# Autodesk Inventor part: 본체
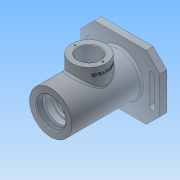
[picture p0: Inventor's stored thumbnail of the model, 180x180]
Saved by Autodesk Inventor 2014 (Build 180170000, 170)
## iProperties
Created: 2017-10
Part Number: 본체
Material: 일반
Document SubType Name: Modeling
Designer: net
Density: 1 g/cm^3
Appearance: 기본값
Mass: 271.768 g
Surface Area: 655.302 cm^2
Volume: 271.768 cm^3
Author: net
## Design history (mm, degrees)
sketch "스케치1"
  geometry: L1 (-58, 47)-(58, 47); L2 (58, 47)-(58, -47); L3 (58, -47)-(-58, -47); L4 (-58, -47)-(-58, 47); C1 r 31 at (0, 0); 3 further points
  constraints: 8 end point, 2 midpoint, 2 parallel, 1 centre point, 1 coincident, 1 horizontal, 1 horizontal alignment, 1 perpendicular, 1 vertical alignment
  dimensions: "d0" = 62 diameter of C1; "d3" = 116 distance of L2.end L3.end; "d4" = 94 distance of L3.end L1.start
extrude "돌출1" new body sketch "스케치1" distance "d5" = 102; taper "d6" = 0 deg; dims "d9" = 10, "d10" = 0
extrude "돌출2" join sketch "스케치1" distance "d7" = 10; taper "d8" = 0 deg
sketch "스케치2"
  geometry: L1 (58, 47)-(-58, 47) reference; L2 (58, -47)-(58, 47) reference; C1 r 35 at (0, 0); 3 further points
  constraints: 2 midpoint, 1 centre point, 1 horizontal alignment, 1 vertical alignment
  dimensions: "d11" = 70 diameter of C1
extrude "돌출3" join sketch "스케치2" distance "d12" = 3; taper "d13" = 0 deg
sketch "스케치3"
  geometry: L1 (31, 102)-(-31, 102) reference; L2 (-35, -13)-(35, -13) reference; L3 (0, 102)-(0, -13); L4 (21, 102)-(21, 93); L5 (21, 93)-(24, 93); L6 (24, 93)-(24, 90); L7 (24, 90)-(20, 90); L8 (20, 90)-(20, 81); L9 (20, 81)-(17.5, 81); L10 (17.5, 81)-(17.5, 77.75); L11 (17.5, 77.75)-(18.5, 77.75); L12 (18.5, 77.75)-(18.5, 76); L13 (18.5, 76)-(17.5, 76); L14 (17.5, 76)-(17.5, 65); L15 (17.5, 65)-(26, 65); L16 (26, 65)-(26, 27); L17 (26, 27)-(17.5, 27); L18 (17.5, 27)-(17.5, 16); L19 (17.5, 16)-(16.5, 16); L20 (16.5, 16)-(16.5, 11); L21 (16.5, 11)-(10, 11); L22 (10, 11)-(10, 8.3); L23 (10, 8.3)-(12.5, 8.3); L24 (12.5, 8.3)-(12.5, 1); L25 (12.5, 1)-(16, 1); L26 (16, 1)-(22, -13); 1 further point
  constraints: 48 end point, 17 parallel, 5 perpendicular, 2 midpoint, 2 point on line, 1 collinear
  dimensions: "d14" = 52 diameter of L16 L3; "d15" = 35 diameter of L14 L3; "d16" = 42 diameter of L4 L3; "d17" = 48 diameter of L6 L3; "d18" = 40 diameter of L8 L3; "d19" = 35 diameter of L10 L3; "d20" = 37 diameter of L12 L3; "d21" = 33 diameter of L20 L3; "d22" = 20 diameter of L22 L3; "d24" = 25 diameter of L24 L3; "d25" = 32 diameter of L25.end L3; "d26" = 44 diameter of L26.end L3; "d27" = 12 distance between parallel lines of L7 L1; "d28" = 3 distance of L5.end L6.end; "d29" = 21 distance between parallel lines of L1 L9; "d30" = 26 distance between parallel lines of L1 L13; "d31" = 1.75 distance of L11.end L12.end; "d32" = 11 distance of L13.end L14.end; "d33" = 38 distance of L15.end L16.end; "d34" = 11 distance of L17.end L18.end; "d35" = 14 distance between parallel lines of L25 L2; "d37" = 7.3 distance of L23.end L24.end; "d38" = 2.7 distance of L21.end L22.end
revolve "회전1" sketch "스케치3" stored, may be unused: angle "d39" = 90 deg
fillet "모깎기1" dims "d43" = 0.3
fillet "모깎기2" dims "d44" = 0.3
feature "스레드1" dims "d45" = 10, "d46" = 0
chamfer "모따기2" distance "d47" = 1; stored, may be unused: second distance "d48" = 2, angle "d49" = 30 deg
sketch "스케치4"
  geometry: L1 (0, 0)-(116, 0) reference; L2 (27, -102)-(89, -102) reference; C1 r 25 at (58, -46); 2 further points
  constraints: 1 centre point, 1 midpoint, 1 vertical alignment
  dimensions: "d50" = 50 diameter of C1; "d51" = 56 distance from line of L2 C1.centre
extrude "돌출4" join sketch "스케치4" stored distance "d52" = 3; taper "d53" = 0 deg
hole "구멍1" diameter "d56" = 32; stored, may be unused: countersink angle "d60" = 90 deg, drill point angle "d62" = 118 deg; dims "d54" = 10, "d55" = 10, "d57" = 6, "d58" = 4, "d59" = 2, "d61" = 34.75
chamfer "모따기3" distance "d63" = 1; stored, may be unused: second distance "d64" = 2, angle "d65" = 30 deg
sketch "스케치5"
  geometry: L1 (-58, -47)-(-58, 47) reference; L2 (46, 20)-(46, -20); L3 (42, 20)-(42, -20); L4 (50, -20)-(50, 20); C1 r 31 at (0, 0) reference; A1 r 4 centre (46, 20) between (50, 20) and (42, 20); A2 r 4 centre (46, -20) between (42, -20) and (50, -20); 1 further point
  constraints: 8 end point, 4 point on circle, 4 tangent, 2 centre point, 2 parallel, 1 horizontal alignment, 1 midpoint
  dimensions: "d66" = 46 distance of point (46, 0) C1.centre; "d67" = 40 distance of L2.end L2.start; "d68" = 4 radius of A1
extrude "돌출5" cut sketch "스케치5" stored distance "d69" = 3; taper "d70" = 0 deg
chamfer "모따기4" distance "d71" = 20; stored, may be unused: second distance "d72" = 2, angle "d73" = 30 deg
fillet "모깎기3" dims "d74" = 3
fillet "모깎기4" dims "d75" = 3
sketch "스케치6"
  geometry: C1 r 25 at (0, 0) reference; 2 further points
  constraints: 1 horizontal alignment
  dimensions: "d76" = 20.5 distance of point (-20.5, 0) C1.centre
hole "구멍2" sketch "스케치6" at (-20.5, 0) diameter "d77" = 2.459; stored, may be unused: countersink angle "d81" = 90 deg, drill point angle "d83" = 118 deg; dims "d78" = 6, "d79" = 4, "d80" = 2, "d82" = 8
fillet "모깎기5" dims "d87" = 3
node "작업 평면1"
sketch "스케치7"
  geometry: L1 (47, 71)-(47, 21) reference; L2 (31, 102)-(-31, 102) reference; 2 further points
  constraints: 1 other
  dimensions: "d89" = 10 distance from line of point (37, 46) L1; "d90" = 56 distance from line of L2 point (37, 46)
feature "엠보싱1" sketch "스케치7" dims "d91" = 0.5, "d92" = 0
fillet "모깎기6" dims "d93" = 3
chamfer "모따기5" distance "d94" = 0.7; stored, may be unused: second distance "d95" = 2, angle "d96" = 30 deg
node "솔리드1"
mirror "대칭1"
pattern_circular "원형 패턴1" dims angle "d85" = 360 deg
other parameters: "d88" = 31
